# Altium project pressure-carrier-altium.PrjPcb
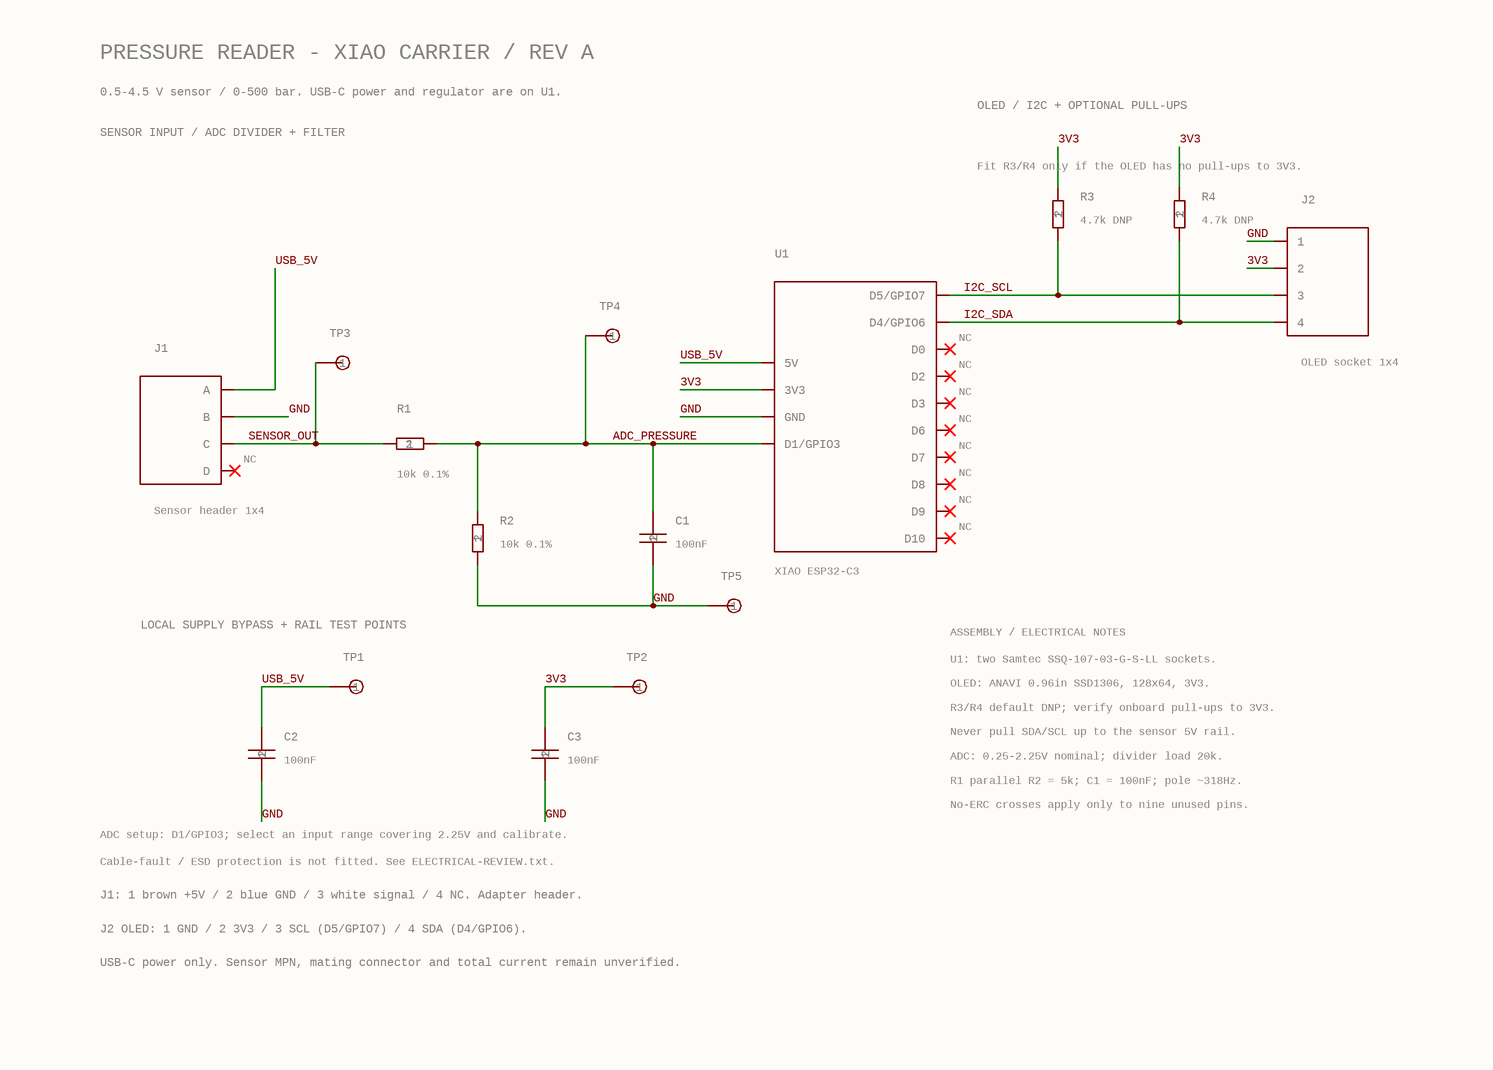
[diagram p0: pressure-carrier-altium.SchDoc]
1 sheet, 15 parts. Net scope: global (net labels, ports and power ports of the same name join across sheets).
Board file: pressure-carrier-altium.PcbDoc

## Sheet pressure-carrier-altium.SchDoc
size 279 x 199 mm; Origin: Eagle; OriginPath: C:\Users\fawn\Downloads\pressure-carrier-altium-pcb\pressure-carrier-altium.sch; OriginSheet: 1

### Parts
C1  100nF  [TDK_C1608_0603]
C2  100nF  [TDK_C1608_0603]
C3  100nF  [TDK_C1608_0603]
J1  Sensor header 1x4  [Samtec_TSW104_THT]
J2  OLED socket 1x4  [Samtec_SSQ104_LL_THT]
R1  10k 0.1%  [YAGEO_RT0603_1608]
R2  10k 0.1%  [YAGEO_RT0603_1608]
R3  4.7k DNP  [YAGEO_AC0603_1608]
R4  4.7k DNP  [YAGEO_AC0603_1608]
TP1  Bare PCB test pad  [PCB_TestPad_PTH_1p2_D1p8]  (value not drawn)
TP2  Bare PCB test pad  [PCB_TestPad_PTH_1p2_D1p8]  (value not drawn)
TP3  Bare PCB test pad  [PCB_TestPad_PTH_1p2_D1p8]  (value not drawn)
TP4  Bare PCB test pad  [PCB_TestPad_PTH_1p2_D1p8]  (value not drawn)
TP5  Bare PCB test pad  [PCB_TestPad_PTH_1p2_D1p8]  (value not drawn)
U1  XIAO ESP32-C3  [Seeed_XIAO_ESP32C3_THT]

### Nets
3V3: C3.1 J2.2 R3.1 R4.1 TP2.1 U1.12(3V3)
ADC_PRESSURE: C1.1 R1.2 R2.1 TP4.1 U1.2(D1/GPIO3)
GND: C1.2 C2.2 C3.2 J1.2(B) J2.1 R2.2 TP5.1 U1.13(GND)
I2C_SCL: J2.3 R3.2 U1.6(D5/GPIO7)
I2C_SDA: J2.4 R4.2 U1.5(D4/GPIO6)
SENSOR_OUT: J1.3(C) R1.1 TP3.1
USB_5V: C2.1 J1.1(A) TP1.1 U1.14(5V)

Not connected (* = marked no-connect by the designer): J1 4(D)*; U1 1(D0)* 3(D2)* 4(D3)* 7(D6)* 8(D7)* 9(D8)* 10(D9)* 11(D10)*

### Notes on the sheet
- PRESSURE READER - XIAO CARRIER / REV A
- 0.5-4.5 V sensor / 0-500 bar. USB-C power and regulator are on U1.
- SENSOR INPUT / ADC DIVIDER + FILTER
- OLED / I2C + OPTIONAL PULL-UPS
- Fit R3/R4 only if the OLED has no pull-ups to 3V3.
- (near U1) NC
- (near J1) NC
- LOCAL SUPPLY BYPASS + RAIL TEST POINTS
- ASSEMBLY / ELECTRICAL NOTES
- U1: two Samtec SSQ-107-03-G-S-LL sockets.
- OLED: ANAVI 0.96in SSD1306, 128x64, 3V3.
- R3/R4 default DNP; verify onboard pull-ups to 3V3.
- Never pull SDA/SCL up to the sensor 5V rail.
- ADC: 0.25-2.25V nominal; divider load 20k.
- R1 parallel R2 = 5k; C1 = 100nF; pole ~318Hz.
- No-ERC crosses apply only to nine unused pins.
- ADC setup: D1/GPIO3; select an input range covering 2.25V and calibrate.
- Cable-fault / ESD protection is not fitted. See ELECTRICAL-REVIEW.txt.
- J1: 1 brown +5V / 2 blue GND / 3 white signal / 4 NC. Adapter header.
- J2 OLED: 1 GND / 2 3V3 / 3 SCL (D5/GPIO7) / 4 SDA (D4/GPIO6).
- USB-C power only. Sensor MPN, mating connector and total current remain unverified.

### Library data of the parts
C1 = C1: Manufacturer: TDK; Manufacturer Part Number: C1608X7R1H104K080AA; Part Kind: Manufacturer part; GateName_1: G$1; ASSEMBLY: Fit; 100nF, 10%, X7R, 50V, 0603; 0.8mm square reflow lands.; Populate: Yes
C2 = C2: Manufacturer: TDK; Manufacturer Part Number: C1608X7R1H104K080AA; Part Kind: Manufacturer part; GateName_1: G$1; ASSEMBLY: Fit; 100nF, 10%, X7R, 50V, 0603; 0.8mm square reflow lands.; Populate: Yes
C3 = C3: Manufacturer: TDK; Manufacturer Part Number: C1608X7R1H104K080AA; Part Kind: Manufacturer part; GateName_1: G$1; ASSEMBLY: Fit; 100nF, 10%, X7R, 50V, 0603; 0.8mm square reflow lands.; Populate: Yes
J1 = J1: Manufacturer: Samtec; Manufacturer Part Number: TSW-104-07-T-S; Part Kind: Manufacturer part; GateName_1: G$1; ASSEMBLY: 2.54mm male adapter header; external sensor cable mating not established.; Populate: Yes; External Sensor Reference: MGPR guide ch4: 0-50MPaG, 5V supply, 0.5-4.5V signal; Cable Mapping: Brown +5V; blue GND; white signal; fourth NC after verification; Mating Status: 2.54mm adapter; exact photographed Molex series not identified
J2 = J2: Manufacturer: Samtec; Manufacturer Part Number: SSQ-104-03-G-S-LL; Part Kind: Manufacturer part; GateName_1: G$1; ASSEMBLY: 2.54mm female socket with locking leads; confirm external OLED pin order.; Populate: Yes; External Display Reference: ANAVI 0.96-inch 128x64 yellow/blue SSD1306 I2C OLED; OLED Interface: Pin1 GND; pin2 3V3; pin3 D5/GPIO7 SCL; pin4 D4/GPIO6 SDA
R1 = R1: Manufacturer: YAGEO; Manufacturer Part Number: RT0603BRD0710KL; Part Kind: Manufacturer part; GateName_1: G$1; ASSEMBLY: Fit; 10k, 0.1%, 0.1W thin-film, 0603.; Populate: Yes
R2 = R2: Manufacturer: YAGEO; Manufacturer Part Number: RT0603BRD0710KL; Part Kind: Manufacturer part; GateName_1: G$1; ASSEMBLY: Fit; 10k, 0.1%, 0.1W thin-film, 0603.; Populate: Yes
R3 = R3: Manufacturer: YAGEO; Manufacturer Part Number: AC0603FR-074K7L; Part Kind: Manufacturer part; GateName_1: G$1; ASSEMBLY: DNP if OLED already has suitable pull-ups; 4.7k, 1%, 0.1W, 0603.; Populate: No
R4 = R4: Manufacturer: YAGEO; Manufacturer Part Number: AC0603FR-074K7L; Part Kind: Manufacturer part; GateName_1: G$1; ASSEMBLY: DNP if OLED already has suitable pull-ups; 4.7k, 1%, 0.1W, 0603.; Populate: No
TP1 = TP1: Part Kind: PCB feature; GateName_1: G$1; ASSEMBLY: Bare plated PCB feature; no purchased component. 1.2mm hole, 1.8mm copper.; Populate: No
TP2 = TP2: Part Kind: PCB feature; GateName_1: G$1; ASSEMBLY: Bare plated PCB feature; no purchased component. 1.2mm hole, 1.8mm copper.; Populate: No
TP3 = TP3: Part Kind: PCB feature; GateName_1: G$1; ASSEMBLY: Bare plated PCB feature; no purchased component. 1.2mm hole, 1.8mm copper.; Populate: No
TP4 = TP4: Part Kind: PCB feature; GateName_1: G$1; ASSEMBLY: Bare plated PCB feature; no purchased component. 1.2mm hole, 1.8mm copper.; Populate: No
TP5 = TP5: Part Kind: PCB feature; GateName_1: G$1; ASSEMBLY: Bare plated PCB feature; no purchased component. 1.2mm hole, 1.8mm copper.; Populate: No
U1 = U1: Manufacturer: Seeed Studio; Manufacturer Part Number: 113991054; Part Kind: Manufacturer part; Socket Manufacturer: Samtec; Socket MPN: SSQ-107-03-G-S-LL; GateName_1: G$1; ASSEMBLY: Through-hole module mounting; official Seeed land pattern, rotated 180 degrees.; Populate: Yes; Socket Quantity: 2; Socket Drill: 1.02mm finished hole; 1.6mm copper pad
